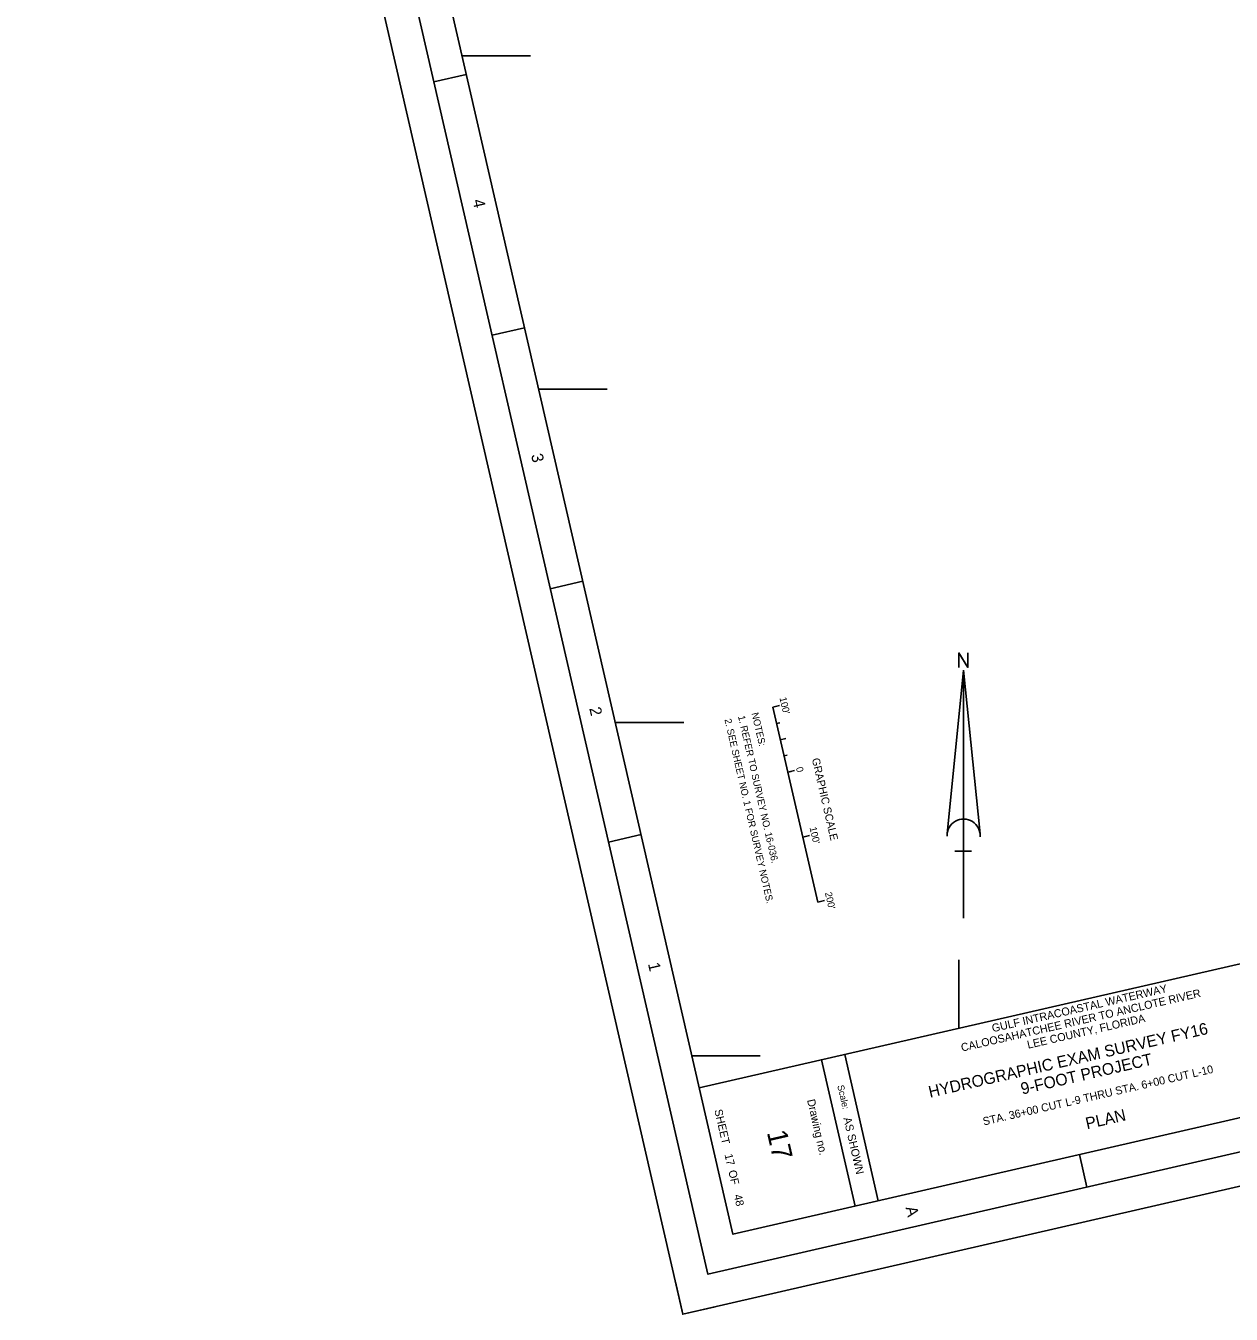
# Model space of a CAD drawing. Extents: x 604101 to 608400, y 789112 to 794162.
# Drawn here: x 604101 to 605908, y 789112 to 791045 of the extents above; entities that cross this region are included whole.
import ezdxf

# ---------------------------------------------------------------- set-up
doc = ezdxf.new("R2010")
doc.units = 0
for name, color, linetype in [('G-ANNO-NPLT', 7, 'Continuous'), ('G-ANNO-TEXT-DRWG', 7, 'Continuous'), ('G-ANNO-TEXT-PROJ', 7, 'Continuous'), ('G-ANNO-TEXT-TTLB', 7, 'Continuous'), ('G-ANNO-TTLB', 7, 'Continuous'), ('V-ANNO-NOTE', 7, 'Continuous'), ('V-ANNO-SYMB', 7, 'Continuous'), ('V-TOPO-COOR-STAT', 7, 'Continuous')]:
    doc.layers.add(name, color=color, linetype=linetype)

msp = doc.modelspace()

# ---------------------------------------------------------------- linework, layer by layer
at = {"layer": 'G-ANNO-NPLT'}
msp.add_lwpolyline([(607414.4, 794162.2), (608399.7, 789874), (605086.1, 789112.6), (604100.8, 793400.8)], close=True, dxfattribs=at)
msp.add_lwpolyline([(605134.8, 789123.7), (605086.1, 789112.5), (605074.9, 789161.2)], dxfattribs=at)
at = {"layer": 'G-ANNO-TTLB'}
for p, q in [((604712.7, 790960.9), (604761.4, 790972.1)), ((604800, 790580.8), (604848.8, 790592)), ((604887.4, 790200.7), (604936.1, 790211.9)), ((608229.5, 790168.3), (605110.8, 789451.8)), ((604974.7, 789820.6), (605023.4, 789831.8)), ((605294.1, 789493.9), (605344.5, 789274.6)), ((605328.8, 789501.9), (605379.2, 789282.6)), ((605692.1, 789303.1), (605680.9, 789351.9))]:
    msp.add_line(p, q, dxfattribs=at)
for points in [[(604160.7, 793363.3), (605123.6, 789172.5), (608339.8, 789911.5), (607376.9, 794102.3)], [(608279.9, 789949), (607356.2, 793969.2), (604237.4, 793252.7), (605161.2, 789232.4)]]:
    msp.add_lwpolyline(points, close=True, dxfattribs=at)
at = {"layer": 'V-ANNO-NOTE'}
for p, q in [((605221.1, 790023), (605231.3, 790025.3)), ((605221.1, 790023), (605288.3, 789730.6)), ((605226.7, 789998.6), (605231.4, 789999.7)), ((605232.3, 789974.2), (605240.6, 789976.2)), ((605237.9, 789949.9), (605242.6, 789951)), ((605243.5, 789925.5), (605253.7, 789927.9)), ((605243.5, 789925.5), (605253.7, 789927.9)), ((605243.5, 789925.5), (605248.4, 789926.6)), ((605265.9, 789828.1), (605276.1, 789830.4)), ((605288.3, 789730.6), (605298.5, 789732.9))]:
    msp.add_line(p, q, dxfattribs=at)
at = {"layer": 'V-ANNO-SYMB'}
for p, q in [((605482.4, 789832.9), (605507.1, 790078.7)), ((605507.1, 789706.3), (605507.1, 790078.7)), ((605531.8, 789832.9), (605507.1, 790078.7)), ((605518.9, 789806.9), (605494, 789806.9))]:
    msp.add_line(p, q, dxfattribs=at)
msp.add_lwpolyline([(605500.2, 790082.7), (605500.2, 790104.4), (605513.7, 790082.7), (605513.7, 790104.4)], dxfattribs=at)
msp.add_arc((605507.1, 789830.4), 24.8, 355.2984, 182.0673, dxfattribs=at)
at = {"layer": 'V-TOPO-COOR-STAT'}
for p, q in [((604755, 791000), (604857.6, 791000)), ((604869.9, 790500), (604972.5, 790500)), ((604984.8, 790000), (605087.4, 790000)), ((605500, 789541.2), (605500, 789643.8)), ((605099.7, 789500), (605202.3, 789500))]:
    msp.add_line(p, q, dxfattribs=at)

# ---------------------------------------------------------------- texts
at = {"layer": 'G-ANNO-TEXT-DRWG'}
for s, height, rotation, p in [('STA. 36+00 CUT L-9 THRU STA. 6+00 CUT L-10', 12, 12.9401, (605537.4, 789395.5)), ('PLAN', 17.5, 12.9401, (605692.2, 789389.8)), ('17', 30, 282.9401, (605212, 789385.3)), (' 17          48', 12, 282.9401, (605147.6, 789356.1))]:
    msp.add_text(s, height=height, rotation=rotation, dxfattribs=at).set_placement(p)
at = {"layer": 'G-ANNO-TEXT-PROJ'}
for s, height, p in [('CALOOSAHATCHEE RIVER TO ANCLOTE RIVER', 12, (605504.7, 789506.3)), ('GULF INTRACOASTAL WATERWAY', 12, (605551, 789535.4)), ('HYDROGRAPHIC EXAM SURVEY FY16', 17.5, (605456.7, 789437.1)), ('LEE COUNTY, FLORIDA', 12, (605603.9, 789510.6)), ('9-FOOT PROJECT', 17.5, (605595, 789441.9))]:
    msp.add_text(s, height=height, rotation=12.9401, dxfattribs=at).set_placement(p)
at = {"layer": 'G-ANNO-TEXT-TTLB'}
for s, height, p in [('Scale:', 10, (605317.7, 789455.1)), ('Drawing no.', 12, (605272.3, 789433.6)), ('SHEET         OF', 12, (605133.3, 789418.5)), ('AS SHOWN', 12, (605326.8, 789406.5))]:
    msp.add_text(s, height=height, rotation=282.9401, dxfattribs=at).set_placement(p)
at = {"layer": 'G-ANNO-TTLB'}
for s, p in [('4', (604770.7, 790783)), ('3', (604858.4, 790401.2)), ('2', (604945.7, 790021.3)), ('1', (605033.7, 789638.1)), ('A', (605420, 789272.4))]:
    msp.add_text(s, height=17.5, rotation=282.9401, dxfattribs=at).set_placement(p)
at = {"layer": 'V-ANNO-NOTE'}
for s, height, p in [("100'", 10.42, (605231, 790036.9)), ('NOTES:', 10.42, (605189.1, 790013.8)), ('2. SEE SHEET NO. 1 FOR SURVEY NOTES.', 10.416, (605148.5, 790004.5)), ('1. REFER TO SURVEY NO. 16-036.', 10.416, (605168.8, 790009.2)), ('GRAPHIC SCALE', 11.666, (605279.5, 789945.3)), ('0', 10.4, (605255.7, 789932.1)), ("100'", 10.42, (605276.1, 789842.3)), ("200'", 10.42, (605299.1, 789744.4))]:
    msp.add_text(s, height=height, rotation=282.9401, dxfattribs=at).set_placement(p)

doc.saveas('drawing.dxf')
